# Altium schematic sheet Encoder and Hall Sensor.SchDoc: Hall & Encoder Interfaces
size A3; CompanyName: Hitex GmbH; Address1: Greschbachstr. 12; Address2: 76229 Karlsruhe, Germany; Address3: www.hitex.com; DocumentNumber: 3; SheetNumber: 3; SheetTotal: 8; PageSetup: Record=PageOptions¦CenterHorizontal=True¦CenterVertical=True¦PrintScale=1.04¦XCorrection=1.00¦YCorrection=1.00¦PrintKind=0¦BorderSize=5000000¦LeftOffset=0¦BottomOffset=0¦Orientation=2¦PaperLength=1000¦PaperWidth=1000¦Scale=100¦PaperSource=7¦PrintQuality=1200¦MediaType=1¦DitherType=10¦PaperKind=A3¦PrintScaleMode=1
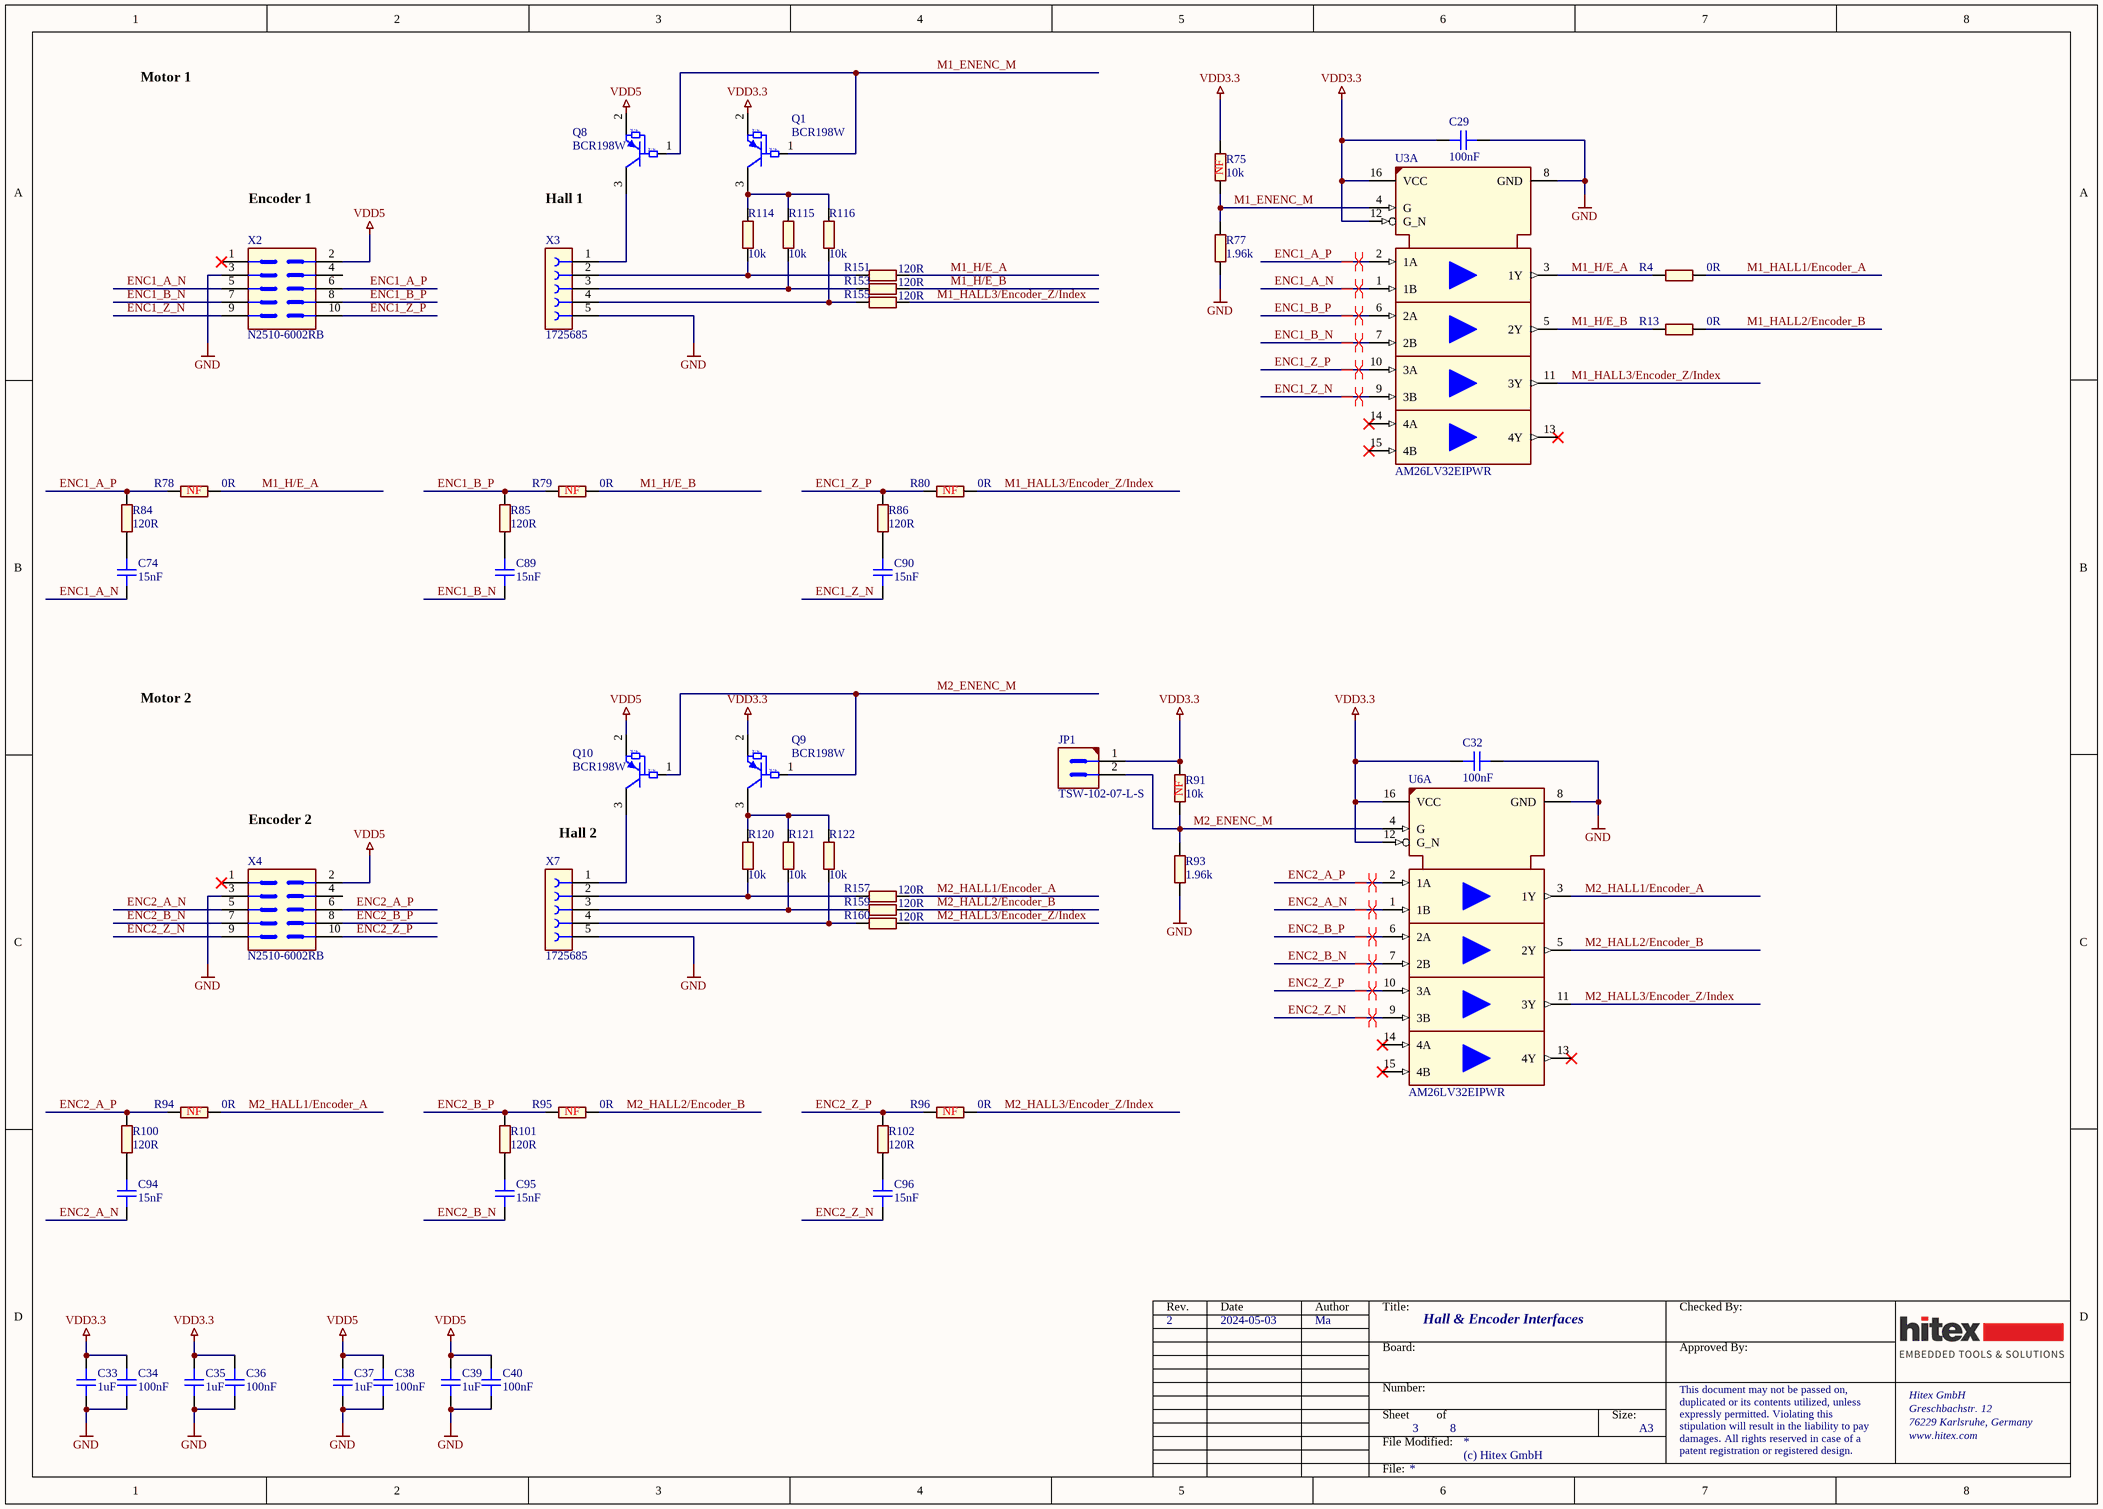
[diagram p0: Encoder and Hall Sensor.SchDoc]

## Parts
C29  100nF  [CAPC1005X55N-0]
C32  100nF  [CAPC1005X55N-0]
C33  1uF  [CAPC1608X90N-1]
C34  100nF  [CAPC1005X55N-0]
C35  1uF  [CAPC1608X90N-1]
C36  100nF  [CAPC1005X55N-0]
C37  1uF  [CAPC1608X90N-1]
C38  100nF  [CAPC1005X55N-0]
C39  1uF  [CAPC1608X90N-1]
C40  100nF  [CAPC1005X55N-0]
C74  15nF  [CAPC1005X55N-0]
C89  15nF  [CAPC1005X55N-0]
C90  15nF  [CAPC1005X55N-0]
C94  15nF  [CAPC1005X55N-0]
C95  15nF  [CAPC1005X55N-0]
C96  15nF  [CAPC1005X55N-0]
JP1  TSW-102-07-L-S  [CON-M-THT-TSW-102-07-L-S]
Q1  BCR198W  [SOT323-3AN]
Q8  BCR198W  [SOT323-3AN]
Q9  BCR198W  [SOT323-3AN]
Q10  BCR198W  [SOT323-3AN]
R4  0R  [RESC1005X03N]
R13  0R  [RESC1005X03N]
R75  10k  [RESC1005X40N]
R77  1.96k  [RESC1005X40N]
R78  0R  [RESC1005X03N]
R79  0R  [RESC1005X03N]
R80  0R  [RESC1005X03N]
R84  120R  [RESC1005X40N]
R85  120R  [RESC1005X40N]
R86  120R  [RESC1005X40N]
R91  10k  [RESC1005X40N]
R93  1.96k  [RESC1005X40N]
R94  0R  [RESC1005X03N]
R95  0R  [RESC1005X03N]
R96  0R  [RESC1005X03N]
R100  120R  [RESC1005X40N]
R101  120R  [RESC1005X40N]
R102  120R  [RESC1005X40N]
R114  10k  [RESC1005X40N]
R115  10k  [RESC1005X40N]
R116  10k  [RESC1005X40N]
R120  10k  [RESC1005X40N]
R121  10k  [RESC1005X40N]
R122  10k  [RESC1005X40N]
R151  120R  [RESC1005X40N]
R153  120R  [RESC1005X40N]
R155  120R  [RESC1005X40N]
R157  120R  [RESC1005X40N]
R159  120R  [RESC1005X40N]
R160  120R  [RESC1005X40N]
U3  AM26LV32EIPWR  [SOP65P640X120-16N-2]  (part A of 5)
U6  AM26LV32EIPWR  [SOP65P640X120-16N-2]  (part A of 5)
X2  N2510-6002RB  [CON-M-THT-N2510-6002RB]
X3  1725685  [CON-TER-THT-1725685]
X4  N2510-6002RB  [CON-M-THT-N2510-6002RB]
X7  1725685  [CON-TER-THT-1725685]

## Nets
GND: C29.2 C32.2 C33.1 C34.1 C35.1 C36.1 C37.1 C38.1 C39.1 C40.1 R77.1 R93.1 U3.8(GND) U6.8(GND) X2.3 X3.5 X4.3 X7.5
VDD3.3: C29.1 C32.1 C33.2 C34.2 C35.2 C36.2 JP1.1 Q1.2(E) Q9.2(E) R75.2 R91.2 U3.12(G_N) U3.16(VCC) U6.12(G_N) U6.16(VCC)
VDD5: C37.2 C38.2 C39.2 C40.2 Q8.2(E) Q10.2(E) X2.2 X4.2
ENC1_A_N: C74.2 U3.1(1B) X2.5
ENC1_A_P: R78.2 R84.2 U3.2(1A) X2.6
ENC1_B_N: C89.2 U3.7(2B) X2.7
ENC1_B_P: R79.2 R85.2 U3.6(2A) X2.8
ENC1_Z_N: C90.2 U3.9(3B) X2.9
ENC1_Z_P: R80.2 R86.2 U3.10(3A) X2.10
ENC2_A_N: C94.2 U6.1(1B) X4.5
ENC2_A_P: R94.2 R100.2 U6.2(1A) X4.6
ENC2_B_N: C95.2 U6.7(2B) X4.7
ENC2_B_P: R95.2 R101.2 U6.6(2A) X4.8
ENC2_Z_N: C96.2 U6.9(3B) X4.9
ENC2_Z_P: R96.2 R102.2 U6.10(3A) X4.10
M1_ENENC_M: Q1.1(B) Q8.1(B) R75.1 R77.2 U3.4(G)
M1_H/E_A: R4.2 R78.1 R151.1 U3.3(1Y)
M1_H/E_B: R13.2 R79.1 R153.1 U3.5(2Y)
M1_HALL1/Encoder_A: R4.1
M1_HALL2/Encoder_B: R13.1
M1_HALL3/Encoder_Z/Index: R80.1 R155.1 U3.11(3Y)
M2_ENENC_M: JP1.2 Q9.1(B) Q10.1(B) R91.1 R93.2 U6.4(G)
M2_HALL1/Encoder_A: R94.1 R157.1 U6.3(1Y)
M2_HALL2/Encoder_B: R95.1 R159.1 U6.5(2Y)
M2_HALL3/Encoder_Z/Index: R96.1 R160.1 U6.11(3Y)
NetC74_1: C74.1 R84.1
NetC89_1: C89.1 R85.1
NetC90_1: C90.1 R86.1
NetC94_1: C94.1 R100.1
NetC95_1: C95.1 R101.1
NetC96_1: C96.1 R102.1
NetQ1_3: Q1.3(C) R114.2 R115.2 R116.2
NetQ8_3: Q8.3(C) X3.1
NetQ9_3: Q9.3(C) R120.2 R121.2 R122.2
NetQ10_3: Q10.3(C) X7.1
NetR114_1: R114.1 R151.2 X3.2
NetR115_1: R115.1 R153.2 X3.3
NetR116_1: R116.1 R155.2 X3.4
NetR120_1: R120.1 R157.2 X7.2
NetR121_1: R121.1 R159.2 X7.3
NetR122_1: R122.1 R160.2 X7.4

Not connected (* = marked no-connect by the designer): U3 13(4Y)* 14(4A)* 15(4B)*; U6 13(4Y)* 14(4A)* 15(4B)*; X2 1* 4; X4 1* 4

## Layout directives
differential pair; differential pair class DIFF120R: ENC1_A_N, ENC1_A_P, ENC1_B_N, ENC1_B_P, ENC1_Z_N, ENC1_Z_P, ENC2_A_N, ENC2_A_P, ENC2_B_N, ENC2_B_P, ENC2_Z_N, ENC2_Z_P

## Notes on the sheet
- Motor 1
- (near R75) NF
- Encoder 1
- Hall 1
- (near R78) NF
- (near R79) NF
- (near R80) NF
- Motor 2
- Encoder 2
- Hall 2
- (near R91) NF
- (near R94) NF
- (near R95) NF
- (near R96) NF
- 2
- 2024-05-03
- Ma

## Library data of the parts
C29 C32 C34 C36 C38 C40 = 310625: CAP / CERA / 100nF / 50V / 10% / X7R (EIA) / -55°C to 125°C / 0402(1005) / SMD / -; Multiple Parts: No; Legacy PartNumber: CAP01010920; Manufacturer: MuRata; Manufacturer Order Number: GRM155R71H104KE14D; Symbol Type: Capacitor; Single; Standard; 2 Pins; Alternate View: Yes; Article Number: 310625; Version Number: V01; Combined Parameters: TC:X7R (EIA);Tol.:-10%/+10%;Vdc:50V; QuickPick: 100nF / 50V / 10% / X7R (EIA) / 0402 (1005M); Type: Standard; Style: Single; Package Metric: 1005; Package Imperial: 0402; ComponentStatus: Released; PLMStatus: Active; HTX: 01.22.0596.0
C33 C35 C37 C39 = 668123: CAP / CERA / 1uF / 25V / 10% / X7R (EIA) / -55°C to 125°C / 0603 / SMD / -; Multiple Parts: No; Manufacturer: Samsung; Manufacturer Order Number: CL10B105KA8NNNC; Symbol Type: Capacitor; Single; Standard; 2 Pins; Alternate View: Yes; Article Number: 668123; Version Number: V00; Combined Parameters: TC:X7R (EIA);Tol.:-10%/+10%;Vdc:25V; QuickPick: 1uF / 25V / 10% / X7R (EIA) / 0603; Type: Standard; Style: Single; ComponentStatus: Released; PLMStatus: Active; HTX: 01.22.0270.0
C74 C89 C90 C94-C96 = 289336: CAP / CERA / 15nF / 50V / 20% / X7R (EIA) / -55°C to 125°C / 0402(1005) / SMD / -; Multiple Parts: No; Legacy PartNumber: CAP01006940; Manufacturer: MuRata; Manufacturer Order Number: GCM155R71H153MA55; Symbol Type: Capacitor; Single; Standard; 2 Pins; Alternate View: Yes; Article Number: 289336; Version Number: V01; Combined Parameters: TC:X7R (EIA);Tol.:-20%/+20%;Vdc:50V; QuickPick: 15nF / 50V / 20% / X7R (EIA) / 0402 (1005); Type: Standard; Style: Single; Automotive Qualified: AEC Q200; Package Metric: 1005; Package Imperial: 0402; ComponentStatus: Released; PLMStatus: Active; HTX: 01.22.0662.0
JP1 = 382904: Through hole .025 SQ Post Header, 2.54mm pitch, 2 pin, vertical, single row; Legacy PartNumber: CON01500574; Manufacturer: Samtec; Alternat View: Yes; Article Number: 382904; Version Number: V01; Legacy DeviceID: SAM_TSW-102-07-L-S; Combined Parameters: Board-to-Board Header (male);2x1;Mounting:THT;Orient:0° (vertical);Shielded:No; QuickPick: 0° (vertical) / Board-to-Board; Style: Strip; Automotive Qualified: No; ComponentStatus: Released; PLMStatus: Active; Voltage DC (max): na; HTX: 03.20.0001.0
Q1 Q8-Q10 = BCR198W: PNP-Digital Transistor  50V, 100mA, R1=R2=47k, SOT-323; PartNumber: 00.94.0133.0; Manufacturer: Infineon Technologies AG; ManufacturerPartNo (2nd Source): PDTA144EU,115; Manufacturer (2nd Source): Nexperia; Designer: Ma; CheckOrientation: true
R4 R13 R78-R80 R94-R96 = 327372: RES / STD / 0R / 63mW / 0R / 0ppm/K / -55°C to 155°C / 0402(1005) / SMD / -; Multiple Parts: No; Legacy PartNumber: RES00000001; Manufacturer: Yageo; Manufacturer Order Number: RC0402JR-070RL; Symbol Type: Resistor; Single; Standard; 2 Pins; Alternate View: Yes; Article Number: 327372; Version Number: V01; Combined Parameters: TCR:0ppm/K;Tol.:-0R/+0R;Vdc:50V;Idc:1A;P:63mW; QuickPick: 0R / 0R / 0.063 / 0402 (1005); Style: Single; Package Metric: 1005; Package Imperial: 0402; ComponentStatus: Released; PLMStatus: Active; Voltage DC (max): 50V; HTX: 01.02.0902.0
R75 R91 R114-R116 R120-R122 = 342167: RES / STD / 10k / 63mW / 1% / 100ppm/K / -55°C to 155°C / 0402(1005) / SMD / -; Multiple Parts: No; Legacy PartNumber: RES01800457; Manufacturer: Vishay; Manufacturer Order Number: CRCW040210K0FK; Symbol Type: Resistor; Single; Standard; 2 Pins; Alternate View: Yes; Article Number: 342167; Version Number: V01; Combined Parameters: TCR:100ppm/K;Tol.:-1%/+1%;Vdc:50V;Idc:-;P:63mW; QuickPick: 10k / 1% / 0.063 / 0402 (1005); Style: Single; Automotive Qualified: AEC Q200; Package Metric: 1005; Package Imperial: 0402; ComponentStatus: Released; PLMStatus: Active; Voltage DC (max): 50V; HTX: 01.02.0703.0
R77 R93 = 341752: RES / STD / 1.96k / 63mW / 1% / 100ppm/K / -55°C to 155°C / 0402(1005) / SMD / -; Multiple Parts: No; Legacy PartNumber: RES01800374; Manufacturer: Vishay; Manufacturer Order Number: CRCW04021K96FK; Symbol Type: Resistor; Single; Standard; 2 Pins; Alternate View: Yes; Article Number: 341752; Version Number: V01; Combined Parameters: TCR:100ppm/K;Tol.:-1%/+1%;Vdc:50V;Idc:-;P:63mW; QuickPick: 1.96k / 1% / 0.063 / 0402 (1005); Style: Single; Automotive Qualified: AEC Q200; Package Metric: 1005; Package Imperial: 0402; ComponentStatus: Released; PLMStatus: Active; Voltage DC (max): 50V; HTX: 01.02.0844.0
R84-R86 R100-R102 R151 R153 R155 R157 R159 R160 = 341067: RES / STD / 120R / 63mW / 1% / 100ppm/K / -55°C to 155°C / 0402(1005) / SMD / -; Multiple Parts: No; Legacy PartNumber: RES01800237; Manufacturer: Vishay; Manufacturer Order Number: CRCW0402120RFK; Symbol Type: Resistor; Single; Standard; 2 Pins; Alternate View: Yes; Article Number: 341067; Version Number: V01; Combined Parameters: TCR:100ppm/K;Tol.:-1%/+1%;Vdc:50V;Idc:-;P:63mW; QuickPick: 120R / 1% / 0.063 / 0402 (1005); Style: Single; Automotive Qualified: AEC Q200; Package Metric: 1005; Package Imperial: 0402; ComponentStatus: Released; PLMStatus: Active; Voltage DC (max): 50V; HTX: 01.02.0728.0
U3 U6 = 767058: Low Voltage High Speed Quadruple Differential Line Receiver With 15 KV IEC ESD Protection; Manufacturer: Texas Instruments; Symbol Type: Low-Voltage High-Speed Quadruple Differential Line Receiver; Alternate View: Yes; Article Number: 767058; Version Number: V00; Legacy DeviceID: TI_AM26LV32EIPWR; Combined Parameters: Protection Driver;Vdc min/max:3V/3.6V;Iout:50mA;Fmax:32MHz; QuickPick: TSSOP16; Automotive Qualified: No; ComponentStatus: Released; PLMStatus: Active; Voltage DC (max): na; HTX: 00.81.0198.0
X2 X4 = 673740: Header, 4-Wall Lo-PRO, .100, Straight, 10Pins, 2.54mm Pitch; Manufacturer: 3M; Article Number: 673740; Version Number: V01; Legacy DeviceID: 3M_N2510-6002RB; Combined Parameters: Board-to-Board Header (male);2x5;Mounting:THT;Orient:0° (vertical);Shielded:No; QuickPick: 0° (vertical) / Board-to-Board; Automotive Qualified: No; ComponentStatus: Released; PLMStatus: Active; Second Source allowed: Yes; Voltage DC (max): na; HTX: 03.13.0017.0
X3 X7 = 646168: PCB terminal block, nominal current: 6 A, rated voltage (III/2)Number of positions per row: 5, pitch: 2.54 mm; Manufacturer: Phoenix Contact; Symbol Type: Socket 5 Pins; Article Number: 646168; Version Number: V01; Legacy DeviceID: PHC_1725685; Combined Parameters: Board-to-Board/Cable Socket (female);5x1;Mounting:THT;Orient:0° (vertical);Shielded:No; QuickPick: 0° (vertical) / Board-to-Board/Cable; Automotive Qualified: No; ComponentStatus: Released; PLMStatus: Active; Second Source allowed: Yes; Voltage DC (max): na; HTX: 03.17.0051.0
